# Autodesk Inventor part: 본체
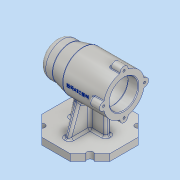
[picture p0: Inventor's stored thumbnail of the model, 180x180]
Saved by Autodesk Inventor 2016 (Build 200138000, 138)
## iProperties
Created: 2021-01
Part Number: 본체
Material: 알루미늄 6061
Document SubType Name: Modeling
Designer: Administrator
Mass: 629.962 g
Surface Area: 613.777 cm^2
Volume: 233.319 cm^3
Density: 2.7 g/cm^3
Appearance: 알루미늄 - 평지
Author: Administrator
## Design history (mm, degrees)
sketch "스케치1"
  geometry: L1 (0, 0)-(0, -100); L2 (22, -100)-(30, -100); L3 (30, -100)-(30, -40); L4 (30, -40)-(25, -20); L5 (25, -20)-(25, -10); L6 (15, 0)-(0, 0); L7 (21, -99)-(21, -85); L8 (21, -85)-(21, -85); L9 (24, -82)-(24, -46); L10 (21, -43)-(21, -43); L11 (21, -43)-(21, -31.3); L12 (20.7, -31)-(17.5, -31); L13 (17.5, -31)-(17.5, -13.3); L14 (17.2, -13)-(16, -13); L15 (16, -13)-(16, -9.3); L16 (15.7, -9)-(10.5, -9); L17 (10.5, -9)-(10.5, -9); L18 (7.5, -6)-(0, -6); L19 (21, -99)-(22, -100); A1 r 3 centre (21, -46) between (24, -46) and (21, -43); A2 r 3 centre (21, -82) between (21, -85) and (24, -82); A3 r 3 centre (7.5, -9) between (10.5, -9) and (7.5, -6); A4 r 0.3 centre (15.7, -9.3) between (16, -9.3) and (15.7, -9); A5 r 0.3 centre (17.2, -13.3) between (17.5, -13.3) and (17.2, -13); A6 r 0.3 centre (20.7, -31.3) between (21, -31.3) and (20.7, -31); A7 r 10 centre (15, -10) between (25, -10) and (15, 0); 4 further points
  constraints: 38 end point, 14 point on circle, 14 tangent, 13 perpendicular, 12 point on line, 7 centre point, 3 equal radius, 2 vertical, 1 parallel
  dimensions: "d0" = 100 distance of L1.start L1.end; "d2" = 60 diameter of L3 L1; "d3" = 20 distance of L4.end point (25, 0); "d4" = 40 vertical distance of L3.end point (25, 0); "d5" = 50 diameter of L5 L1; "d6" = 15 distance between parallel lines of L2 L8; "d7" = 42 distance between parallel lines of L8 L10; "d8" = 12 distance between parallel lines of L10 L12; "d9" = 18 distance between parallel lines of L12 L14; "d10" = 4 distance between parallel lines of L14 L16; "d11" = 3 distance between parallel lines of L16 L18; "d12" = 42 diameter of L7 L1; "d13" = 48 diameter of L9 L1; "d14" = 35 diameter of L13 L1; "d15" = 32 diameter of L15 L1; "d16" = 21 diameter of L17 L1; "d17" = 3 radius of A1; "d18" = 3 radius of A3; "d19" = 0.3 radius of A4; "d20" = 1 distance of L7.start point (21, -100); "d21" = 1 distance of L2.start point (21, -100) (= d20); "d22" = 10 radius of A7
revolve "회전1" sketch "스케치1" stored, may be unused: angle "d23" = 90 deg
sketch "스케치2" dims "d24" = 60
  geometry: C1 r 6 at (0, 30); C2 r 6 at (-30, 0); C3 r 6 at (0, -30); C4 r 6 at (30, 0); 2 further points
  constraints: 4 centre point, 2 vertical alignment, 1 coincident, 11 other
  dimensions: "d25" = 12 diameter of C1; "d28" = 360 deg dimension on point (0, 0) C1.centre (derived)
extrude "돌출1" join sketch "스케치2" distance "d30" = 16; taper "d31" = 0 deg
sketch "스케치3"
  geometry: A1 r 6 centre (0, 0) between (5.97, -0.6) and (-5.97, -0.6) reference; A2 r 6 centre (-30, -30) between (-29.4, -24.03) and (-29.4, -35.97) reference; A3 r 6 centre (0, -60) between (-5.97, -59.4) and (5.97, -59.4) reference; A4 r 6 centre (30, -30) between (29.4, -35.97) and (29.4, -24.03) reference; 5 further points
  constraints: 4 coincident
hole "구멍1" sketch "스케치3" at (0, 0), (-30, -30), (0, -60), (30, -30) diameter "d32" = 3.242; stored, may be unused: countersink angle "d36" = 90 deg, drill point angle "d38" = 118 deg; dims "d33" = 8, "d34" = 4, "d35" = 2, "d37" = 10
fillet "모깎기1" dims "d39" = 3
fillet "모깎기2" dims "d40" = 1
node "작업 평면1"
sketch "스케치4" dims "d42" = 100
  geometry: L1 (50, -70.711)-(20.711, -100); L2 (20.711, -100)-(-20.711, -100); L3 (-20.711, -100)-(-50, -70.711); L4 (-50, -70.711)-(-50, -29.289); L5 (-50, -29.289)-(-20.711, 0); L6 (-20.711, 0)-(20.711, 0); L7 (20.711, 0)-(50, -29.289); L8 (50, -29.289)-(50, -70.711); 4 further points
  constraints: 16 end point, 1 coincident, 1 horizontal alignment, 1 midpoint, 19 other
  dimensions: "d43" = 50 distance of point (0, -50) point (0, 0)
extrude "돌출2" join sketch "스케치4" distance "d44" = 10; taper "d45" = 0 deg
sketch "스케치5"
  geometry: L1 (-26.388, -30.505)-(-65, -23); L2 (-65, -29.289)-(-65, 0) reference; L3 (-75, 0)-(-65, 0) reference; L4 (-26.388, -30.505)-(-26.388, -77); L5 (-26.388, -77)-(-65, -77); L6 (-65, -100)-(-65, -70.711) reference; L7 (-75, -100)-(-65, -100) reference; L8 (-65, -23)-(-65, -77); 2 further points
  constraints: 8 end point, 2 point on line, 1 collinear, 1 perpendicular, 1 vertical
  dimensions: "d76" = 23 distance from line of L3 L1.end; "d77" = 101 deg angle of L2 L1; "d78" = 23 distance between parallel lines of L7 L5
extrude "돌출3" join sketch "스케치5" stored distance "d50" = 8; taper "d51" = 0 deg
node "작업 평면2"
sketch "스케치6"
  geometry: L1 (20.711, -65)-(50, -65) reference; L2 (35, -65)-(26.337, -41.199); L3 (-50, -65)-(-20.711, -65) reference; L4 (-35, -65)-(-26.837, -42.571); L5 (50, -75)-(50, -65) reference; L6 (-50, -75)-(-50, -65) reference; 1 further point
  constraints: 4 end point, 2 point on line
  dimensions: "d53" = 15 distance from line of L5 L2.start; "d54" = 15 distance from line of L6 L4.start; "d55" = 110 deg angle of L1 L2; "d56" = 110 deg angle of L3 L4
feature "리브1" dims "d57" = 1, "d58" = 8, "d59" = 0, "d60" = 0, "d61" = 1, "d62" = 1
feature "리브2" dims "d63" = 1, "d64" = 8, "d65" = 0, "d66" = 0, "d67" = 1, "d68" = 1
sketch "스케치7"
  geometry: L1 (50, 70.711)-(50, 29.289) reference; L2 (50, 50)-(-50, 50); L3 (-50, 29.289)-(-50, 70.711) reference; L4 (-20.711, 100)-(20.711, 100) reference; L5 (0, 100)-(0, 0); L6 (0, 50)-(35.355, 14.645); L7 (50, 29.289)-(20.711, 0) reference; L8 (0, 50)-(-35.355, 14.645); L9 (-20.711, 0)-(-50, 29.289) reference; L10 (0, 50)-(35.355, 85.355); L11 (20.711, 100)-(50, 70.711) reference; L12 (0, 50)-(-35.355, 85.355); L13 (-50, 70.711)-(-20.711, 100) reference; C1 r 4.5 at (35.355, 14.645); C2 r 4.5 at (35.355, 85.355); C3 r 4.5 at (-35.355, 14.645); C4 r 4.5 at (-35.355, 85.355)
  constraints: 12 end point, 8 midpoint, 4 centre point, 4 coincident, 1 vertical
  dimensions: "d69" = 9 diameter of C1; "d70" = 9 diameter of C2; "d71" = 9 diameter of C3; "d72" = 9 diameter of C4
extrude "돌출4" cut sketch "스케치7" distance "d73" = 10; taper "d74" = 0 deg
fillet "모깎기3" dims "d79" = 3
fillet "모깎기4" dims "d80" = 3
fillet "모깎기5" dims "d81" = 3
node "작업 평면3"
sketch "스케치8"
  geometry: L1 (6.771, -100)-(29.226, -100) reference; 2 further points
  constraints: 1 vertical alignment, 1 other
  dimensions: "d83" = 38 distance from line of L1 point (0, -62)
feature "엠보싱1" sketch "스케치8" dims "d0" = 100, "d2" = 60, "d3" = 20, "d4" = 40, "d5" = 50, "d6" = 15, "d7" = 42, "d8" = 12, "d9" = 18, "d10" = 4, "d11" = 3, "d12" = 42, "d13" = 48, "d14" = 35, "d15" = 32, "d16" = 21, "d17" = 3, "d18" = 3, "d19" = 0.3, "d20" = 1, "d21" = 1 (= d20), "d22" = 10, "d84" = 0.5, "d85" = 0
node "솔리드1"
other parameters: "d41" = -75
